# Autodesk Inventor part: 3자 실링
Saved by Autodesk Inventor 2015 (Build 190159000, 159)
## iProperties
Created: 2025-11
Part Number: 3자 실링
Material: 일반
Document SubType Name: Modeling
Designer: user
Density: 1 g/cm^3
Appearance: 기본값
Author: user
Author: jhkim
Creation Date: 2025-10-31
Sending System: Autodesk Inventor 2026
Preprocessor: ST-DEVELOPER v20.1
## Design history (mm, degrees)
node "3자 실링1"
node "솔리드1"
node "기준1"
